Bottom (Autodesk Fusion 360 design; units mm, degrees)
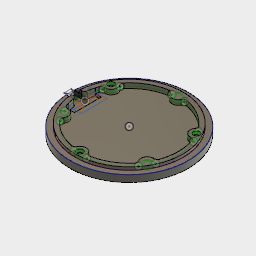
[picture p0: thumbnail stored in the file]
parameter "height" = 10 comment "height of the component"
parameter "rail_height" = 3
parameter "exrtusion_delta_for_magnets" = 0.8
parameter "diameter" = 120
parameter "inner_diameter" = 100
parameter "diameter_offet" = 10
parameter "pressfit_offset" = 1
parameter "magnet_diameter" = 6.4
parameter "magnet_height" = 3.2
parameter "holes_position_from_diameter" = 20
parameter "plateform_height" = 2.5 (= "height / 4")
parameter "plateform_inner_diameter" = 0
parameter "pcb_offet" = 0.5
sketch "base" plane through (0, 0, 0) normal (0, 1, 0) x axis (1, 0, 0)
  circle C1 centre (0, 0) radius 60
  circle C2 centre (0, 0) radius 50
  dimension "d1" diameter C1 = 120 (= "diameter")
  dimension "d63" diameter C2 = 100 (= "inner_diameter")
sketch "arround magnets" plane through (0, 0, 0) normal (0, 1, 0) x axis (1, 0, 0)
  circle C1 centre (0, 50) radius 6.4
  point P1 (0, 0)
  point P2 (0, 50)
  dimension "d124" diameter C1 = 12.8 (= "magnet_diameter * 2")
  dimension "d130" distance P1 P2 = 50 (= "diameter / 2 - holes_position_from_diameter / 2")
extrude "Extrude18" new body sketch "arround magnets" along normal blind 10 (= "height")
circular_pattern "C-Pattern6" TotalAngle 360
extrude "Extrude17" new body sketch "base" profile of C2 along normal blind 10 (= "height")
extrude "Extrude8" new body sketch "base" along normal blind 10 (= "height") bodies "Part A Top"
combine "Combine2"
sketch "top_holes" plane through (0, 10, 0) normal (0, 1, 0) x axis (-1, 0, 0)
  circle C1 centre (0, 50) radius 3.2
  circle C2 centre (-43.3013, -25) radius 3.2
  circle C3 centre (43.3013, -25) radius 3.2
  point P1 (0, 0)
  point P4 (43.3013, -25)
  dimension "d5" diameter C1 = 6.4 (= "magnet_diameter")
  dimension "d94" distance P1 P4 = 50 (= "diameter / 2 - holes_position_from_diameter / 2")
  dimension "d7" C-Pattern1-Angle = 360
extrude "Extrude13" cut sketch "top_holes" no distance stored
sketch "top_rail_out" plane through (0, 10, 0) normal (0, 1, 0) x axis (-1, 0, 0)
  circle C1 centre (0, 0) radius 60
  circle C2 centre (0, 0) radius 54.5
  circle C3 centre (-43.3013, -25) radius 3.2
  circle C4 centre (0, 50) radius 3.2
  circle C5 centre (43.3013, -25) radius 3.2
  arc A1 centre (-43.3013, 25) radius 6.4 clockwise from (-39.7531, 30.3264) to (-46.14, 19.264)
  arc A2 centre (0, 50) radius 6.4 clockwise from (6.3869, 49.5904) to (-6.3869, 49.5904)
  arc A3 centre (43.3013, 25) radius 6.4 clockwise from (46.14, 19.264) to (39.7531, 30.3264)
  arc A4 centre (43.3013, -25) radius 6.4 clockwise from (39.7531, -30.3264) to (46.14, -19.264)
  arc A5 centre (0, -50) radius 6.4 clockwise from (-6.3869, -49.5904) to (6.3869, -49.5904)
  arc A6 centre (-43.3013, -25) radius 6.4 clockwise from (-46.14, -19.264) to (-39.7531, -30.3264)
  arc A7 centre (0, 0) radius 50 clockwise from (-46.14, -19.264) to (-46.14, 19.264)
  arc A8 centre (0, 0) radius 50 clockwise from (-39.7531, 30.3264) to (-6.3869, 49.5904)
  arc A9 centre (0, 0) radius 50 clockwise from (6.3869, 49.5904) to (39.7531, 30.3264)
  arc A10 centre (0, 0) radius 50 clockwise from (46.14, 19.264) to (46.14, -19.264)
  arc A11 centre (0, 0) radius 50 clockwise from (39.7531, -30.3264) to (6.3869, -49.5904)
  arc A12 centre (0, 0) radius 50 clockwise from (-6.3869, -49.5904) to (-39.7531, -30.3264)
  circle C6 centre (0, 0) radius 60
  dimension "d65" diameter C2 = 109 (= "diameter - diameter_offet - pressfit_offset")
  dimension "d96" diameter C1 = 120 (= "diameter")
extrude "Extrude10" cut sketch "top_rail_out" profile of C1 C2 against normal blind 3 (magnitude of "-1 * rail_height")
sketch "bottom_holes" plane through (0, 0, 0) normal (0, -1, 0) x axis (1, 0, 0)
  circle C1 centre (-43.3013, -25) radius 3.2
  point P1 (0, 0)
  point P2 (-43.3013, -25)
  dimension "d57" diameter C1 = 6.4 (= "magnet_diameter")
  dimension "d95" distance P1 P2 = 50 (= "diameter / 2 - holes_position_from_diameter / 2")
sketch "top_rail_in" plane through (0, 10, 0) normal (0, 1, 0) x axis (-1, 0, 0)
  circle C1 centre (56.2917, -32.5) radius 3.175
  circle C2 centre (0, 65) radius 3.175
  circle C3 centre (-56.2917, -32.5) radius 3.175
  circle C4 centre (0, 0) radius 75
  circle C5 centre (0, 0) radius 70
  circle C6 centre (0, 0) radius 60
  circle C7 centre (0, 0) radius 50
  circle C8 centre (0, 0) radius 60
  arc A1 centre (-43.3013, 25) radius 6.4 clockwise from (-39.7531, 30.3264) to (-46.14, 19.264)
  arc A2 centre (0, 50) radius 6.4 clockwise from (6.3869, 49.5904) to (-6.3869, 49.5904)
  arc A3 centre (43.3013, 25) radius 6.4 clockwise from (46.14, 19.264) to (39.7531, 30.3264)
  arc A4 centre (43.3013, -25) radius 6.4 clockwise from (39.7531, -30.3264) to (46.14, -19.264)
  arc A5 centre (0, -50) radius 6.4 clockwise from (-6.3869, -49.5904) to (6.3869, -49.5904)
  arc A6 centre (-43.3013, -25) radius 6.4 clockwise from (-46.14, -19.264) to (-39.7531, -30.3264)
  circle C9 centre (-43.3013, -25) radius 3.2
  circle C10 centre (0, 50) radius 3.2
  circle C11 centre (43.3013, -25) radius 3.2
  circle C12 centre (0, 0) radius 54.5
  arc A7 centre (0, 0) radius 50 clockwise from (-46.14, -19.264) to (-46.14, 19.264)
  arc A8 centre (0, 0) radius 50 clockwise from (-39.7531, 30.3264) to (-6.3869, 49.5904)
  arc A9 centre (0, 0) radius 50 clockwise from (6.3869, 49.5904) to (39.7531, 30.3264)
  arc A10 centre (0, 0) radius 50 clockwise from (46.14, 19.264) to (46.14, -19.264)
  arc A11 centre (0, 0) radius 50 clockwise from (39.7531, -30.3264) to (6.3869, -49.5904)
  arc A12 centre (0, 0) radius 50 clockwise from (-6.3869, -49.5904) to (-39.7531, -30.3264)
  dimension "d35" diameter C6 = 120 (= "diameter")
  dimension "d64" diameter C7 = 100 (= "inner_diameter")
  dimension "d66" diameter C8 = 120 (= "diameter")
work_point "WorkPoint1"
work_axis "WorkAxis1"
sketch "Sketch19" plane through (0, 0, 0) normal (0, -1, 0) x axis (1, 0, 0)
  circle C1 centre (0, 0) radius 50
  arc A1 centre (0, 0) radius 50 clockwise from (39.7531, -30.3264) to (6.3869, -49.5904)
  arc A2 centre (0, -50) radius 6.4 clockwise from (-6.3869, -49.5904) to (6.3869, -49.5904)
  arc A3 centre (0, 0) radius 50 clockwise from (-6.3869, -49.5904) to (-39.7531, -30.3264)
  arc A4 centre (-43.3013, -25) radius 6.4 clockwise from (-46.14, -19.264) to (-39.7531, -30.3264)
  arc A5 centre (0, 0) radius 50 clockwise from (-46.14, -19.264) to (-46.14, 19.264)
  arc A6 centre (-43.3013, 25) radius 6.4 clockwise from (-39.7531, 30.3264) to (-46.14, 19.264)
  arc A7 centre (0, 0) radius 50 clockwise from (-39.7531, 30.3264) to (-6.3869, 49.5904)
  arc A8 centre (0, 50) radius 6.4 clockwise from (6.3869, 49.5904) to (-6.3869, 49.5904)
  arc A9 centre (0, 0) radius 50 clockwise from (6.3869, 49.5904) to (39.7531, 30.3264)
  arc A10 centre (43.3013, 25) radius 6.4 clockwise from (46.14, 19.264) to (39.7531, 30.3264)
  arc A11 centre (0, 0) radius 50 clockwise from (46.14, 19.264) to (46.14, -19.264)
  arc A12 centre (43.3013, -25) radius 6.4 clockwise from (39.7531, -30.3264) to (46.14, -19.264)
  circle C2 centre (0, 0) radius 60
  dimension "d134" diameter C1 = 100 (= "inner_diameter")
  dimension "d132" diameter = 0 (= "plateform_inner_diameter")
extrude "Extrude19" add sketch "Sketch19" profile of C1 A1 A2 A3 A4 A5 A6 A7 A8 A9 A10 A11 A12 against normal blind 5
sketch "Sketch22" plane through (0, 7, 0) normal (0, 1, 0) x axis (-1, 0, 0)
  line L1 (47.5, -3.7) -> (62.5, -3.7)
  line L2 (47.5, 3.7) -> (47.5, -3.7)
  line L3 (62.5, 3.7) -> (47.5, 3.7)
  line L4 (62.5, -3.7) -> (62.5, 3.7)
  line L5 (47.5, 3.7) -> (62.5, -3.7)
  line L6 (62.5, 3.7) -> (47.5, -3.7)
  line L7 (35.5578, -13.2291) -> (54.4422, -13.2291)
  line L8 (35.5578, 13.2291) -> (35.5578, -13.2291)
  line L9 (54.4422, 13.2291) -> (35.5578, 13.2291)
  line L10 (54.4422, -13.2291) -> (54.4422, 13.2291)
  line L11 (35.5578, 13.2291) -> (54.4422, -13.2291)
  line L12 (54.4422, 13.2291) -> (35.5578, -13.2291)
  line L13 (46.9885, -13.2291) -> (43.0115, -13.2291)
  line L14 (46.9885, 13.2291) -> (46.9885, -13.2291)
  line L15 (43.0115, 13.2291) -> (46.9885, 13.2291)
  line L16 (43.0115, -13.2291) -> (43.0115, 13.2291)
  line L17 (46.9885, 13.2291) -> (43.0115, -13.2291)
  line L18 (43.0115, 13.2291) -> (46.9885, -13.2291)
  line L19 (48.2182, -13.2291) -> (52.87, -13.2291)
  line L20 (49.8629, -3.7) -> (54.3743, -3.7)
  line L21 (49.8629, 3.7) -> (54.4422, 3.7)
  circle C1 centre (0, 0) radius 60
  arc A1 centre (43.3013, 25) radius 6.4 clockwise from (46.14, 19.264) to (39.7531, 30.3264)
  arc A2 centre (0, 0) radius 50 clockwise from (6.3869, 49.5904) to (39.7531, 30.3264)
  arc A3 centre (0, 50) radius 6.4 clockwise from (6.3869, 49.5904) to (-6.3869, 49.5904)
  arc A4 centre (0, 0) radius 50 clockwise from (-39.7531, 30.3264) to (-6.3869, 49.5904)
  arc A5 centre (-43.3013, 25) radius 6.4 clockwise from (-39.7531, 30.3264) to (-46.14, 19.264)
  arc A6 centre (0, 0) radius 50 clockwise from (-46.14, -19.264) to (-46.14, 19.264)
  arc A7 centre (-43.3013, -25) radius 6.4 clockwise from (-46.14, -19.264) to (-39.7531, -30.3264)
  arc A8 centre (0, 0) radius 50 clockwise from (-6.3869, -49.5904) to (-39.7531, -30.3264)
  arc A9 centre (0, -50) radius 6.4 clockwise from (-6.3869, -49.5904) to (6.3869, -49.5904)
  arc A10 centre (0, 0) radius 50 clockwise from (39.7531, -30.3264) to (6.3869, -49.5904)
  arc A11 centre (43.3013, -25) radius 6.4 clockwise from (39.7531, -30.3264) to (46.14, -19.264)
  arc A12 centre (0, 0) radius 50 clockwise from (46.14, 19.264) to (46.14, -19.264)
  arc A13 centre (43.3013, 25) radius 6.4 clockwise from (46.14, 19.264) to (39.7531, 30.3264)
  arc A14 centre (0, 0) radius 50 clockwise from (6.3869, 49.5904) to (39.7531, 30.3264)
  arc A15 centre (0, 50) radius 6.4 clockwise from (6.3869, 49.5904) to (-6.3869, 49.5904)
  arc A16 centre (0, 0) radius 50 clockwise from (-39.7531, 30.3264) to (-6.3869, 49.5904)
  arc A17 centre (-43.3013, 25) radius 6.4 clockwise from (-39.7531, 30.3264) to (-46.14, 19.264)
  arc A18 centre (0, 0) radius 50 clockwise from (-46.14, -19.264) to (-46.14, 19.264)
  arc A19 centre (-43.3013, -25) radius 6.4 clockwise from (-46.14, -19.264) to (-39.7531, -30.3264)
  arc A20 centre (0, 0) radius 50 clockwise from (-6.3869, -49.5904) to (-39.7531, -30.3264)
  arc A21 centre (0, -50) radius 6.4 clockwise from (-6.3869, -49.5904) to (6.3869, -49.5904)
  arc A22 centre (0, 0) radius 50 clockwise from (39.7531, -30.3264) to (6.3869, -49.5904)
  arc A23 centre (43.3013, -25) radius 6.4 clockwise from (39.7531, -30.3264) to (46.14, -19.264)
  arc A24 centre (0, 0) radius 50 clockwise from (46.14, 19.264) to (46.14, -19.264)
  circle C2 centre (0, 0) radius 54.5
  circle C3 centre (0, 0) radius 60
  point P4 (47.5, 3.7)
  point P5 (62.5, 3.7)
  point P3 (47.5, -3.7)
  dimension "d142" distance P4 P5 = 15
  dimension "d143" distance P3 P4 = 7.4
  dimension "d144" diameter C1 = 120 (= "diameter")
extrude "Extrude23" new body sketch "Sketch22" profile of L1 L2 L3 L7 L9 L10 C1 L13 L14 L15 L16 A12 A24 C2 C3 against normal blind 4.2 and along normal blind 10
sketch "Sketch25" plane through (0, 7, 0) normal (0, 1, 0) x axis (-1, 0, 0)
  line L1 (59.8858, -3.7) -> (49.8629, -3.7)
  line L2 (49.8629, 3.7) -> (59.8858, 3.7)
  line L3 (43.0115, 13.2291) -> (48.2182, 13.2291)
  line L4 (43.0115, -13.2291) -> (43.0115, 13.2291)
  line L5 (48.2182, -13.2291) -> (43.0115, -13.2291)
  line L6 (60.354, -4.2) -> (50.325, -4.2)
  line L7 (50.325, 4.2) -> (60.354, 4.2)
  line L8 (42.5115, 13.7291) -> (48.598, 13.7291)
  line L9 (42.5115, -13.7291) -> (42.5115, 13.7291)
  line L10 (48.598, -13.7291) -> (42.5115, -13.7291)
  arc A1 centre (0, 0) radius 50 clockwise from (49.8629, -3.7) to (48.2182, -13.2291)
  arc A2 centre (0, 0) radius 60 clockwise from (59.8858, 3.7) to (59.8858, -3.7)
  arc A3 centre (0, 0) radius 50 clockwise from (48.2182, 13.2291) to (49.8629, 3.7)
  arc A4 centre (43.3013, 25) radius 6.4 clockwise from (46.14, 19.264) to (39.7531, 30.3264)
  arc A5 centre (0, 0) radius 50 clockwise from (6.3869, 49.5904) to (39.7531, 30.3264)
  arc A6 centre (0, 50) radius 6.4 clockwise from (6.3869, 49.5904) to (-6.3869, 49.5904)
  arc A7 centre (0, 0) radius 50 clockwise from (-39.7531, 30.3264) to (-6.3869, 49.5904)
  arc A8 centre (-43.3013, 25) radius 6.4 clockwise from (-39.7531, 30.3264) to (-46.14, 19.264)
  arc A9 centre (0, 0) radius 50 clockwise from (-46.14, -19.264) to (-46.14, 19.264)
  arc A10 centre (-43.3013, -25) radius 6.4 clockwise from (-46.14, -19.264) to (-39.7531, -30.3264)
  arc A11 centre (0, 0) radius 50 clockwise from (-6.3869, -49.5904) to (-39.7531, -30.3264)
  arc A12 centre (0, -50) radius 6.4 clockwise from (-6.3869, -49.5904) to (6.3869, -49.5904)
  arc A13 centre (0, 0) radius 50 clockwise from (39.7531, -30.3264) to (6.3869, -49.5904)
  arc A14 centre (43.3013, -25) radius 6.4 clockwise from (39.7531, -30.3264) to (46.14, -19.264)
  arc A15 centre (0, 0) radius 50 clockwise from (46.14, 19.264) to (46.14, -19.264)
  circle C1 centre (0, 0) radius 54.5
  circle C2 centre (0, 0) radius 60
  arc A16 centre (0, 0) radius 50.5 clockwise from (50.325, -4.2) to (48.598, -13.7291)
  arc A17 centre (0, 0) radius 60.5 clockwise from (60.354, 4.2) to (60.354, -4.2)
  arc A18 centre (0, 0) radius 50.5 clockwise from (48.598, 13.7291) to (50.325, 4.2)
  dimension "d169" = 0.5
extrude "Extrude25" new body sketch "Sketch25" profile of A1 L1 A2 L2 A3 L3 L4 L5 A15 C1 C2 A16 L7 L6 L8 A17 L9 A18 L10 against normal blind 4.2 and along normal blind 10
move "Move8" TranslateX 0.5 (= "pcb_offet") TranslateY 0 TranslateZ 0
combine "Combine4"
fillet "Fillet4" radius 3
sketch "Sketch26" plane through (0, 2.8, 0) normal (0, 1, 0) x axis (-1, 0, 0)
  line L1 (52.5133, 4.2) -> (59.8528, 4.2)
  line L2 (42.0115, 13.7291) -> (48.098, 13.7291)
  line L3 (42.0115, -13.7291) -> (42.0115, 13.7291)
  line L4 (48.098, -13.7291) -> (42.0115, -13.7291)
  line L5 (59.8528, -4.2) -> (52.5133, -4.2)
  arc A1 centre (0, 0) radius 60 clockwise from (59.8528, 4.2) to (59.8528, -4.2)
  arc A2 centre (52.5133, 7.2) radius 3 clockwise from (52.5133, 4.2) to (49.5406, 6.7963)
  arc A3 centre (-0.5, 0) radius 50.5 clockwise from (48.098, 13.7291) to (49.5406, 6.7963)
  arc A4 centre (-0.5, 0) radius 50.5 clockwise from (49.5406, -6.7963) to (48.098, -13.7291)
  arc A5 centre (52.5133, -7.2) radius 3 clockwise from (49.5406, -6.7963) to (52.5133, -4.2)
named bodies: "Part A Top"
